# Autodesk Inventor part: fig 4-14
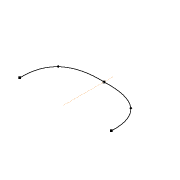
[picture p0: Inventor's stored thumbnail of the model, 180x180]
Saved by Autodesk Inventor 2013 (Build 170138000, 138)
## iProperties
Created: 2012-07
Part Number: fig 4-14
Material: Generic
Document SubType Name: Modeling
Designer: CADCIM
Density: 1 g/cm^3
Author: CADCIM
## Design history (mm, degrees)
sketch "Sketch1"
  geometry: L1 (-0.121, 16.232)-(-0.121, 0.498); 5 further points
  constraints: 2 end point, 2 symmetric about line, 1 vertical, 7 other
